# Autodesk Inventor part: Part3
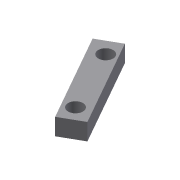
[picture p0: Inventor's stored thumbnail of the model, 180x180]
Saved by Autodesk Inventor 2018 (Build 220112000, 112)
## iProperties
Created: 2017-05
Part Number: Part3
Material: Generic
Document SubType Name: Modeling
Designer: CADCIM 00
Density: 1 g/cm^3
Appearance: Default
Author: CADCIM 00
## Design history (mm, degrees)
sketch "Sketch1"
  geometry: L1 (-30.267, 40.394)-(-1.138, -10.969); L2 (-1.138, -10.969)-(11.085, -4.037); L3 (11.085, -4.037)-(-18.043, 47.326); L4 (-18.043, 47.326)-(-30.267, 40.394); C1 r 4.406 at (-18.304, 36.224) reference; C2 r 4.406 at (0, 0) reference; 1 further point
  constraints: 8 end point, 2 parallel, 1 perpendicular
extrude "Extrusion1" new body sketch "Sketch1" distance "d0" = 10; taper "d1" = 0 deg
body "Solid1"
node "Reference1"
node "Reference2"
